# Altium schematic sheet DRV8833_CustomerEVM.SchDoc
size B
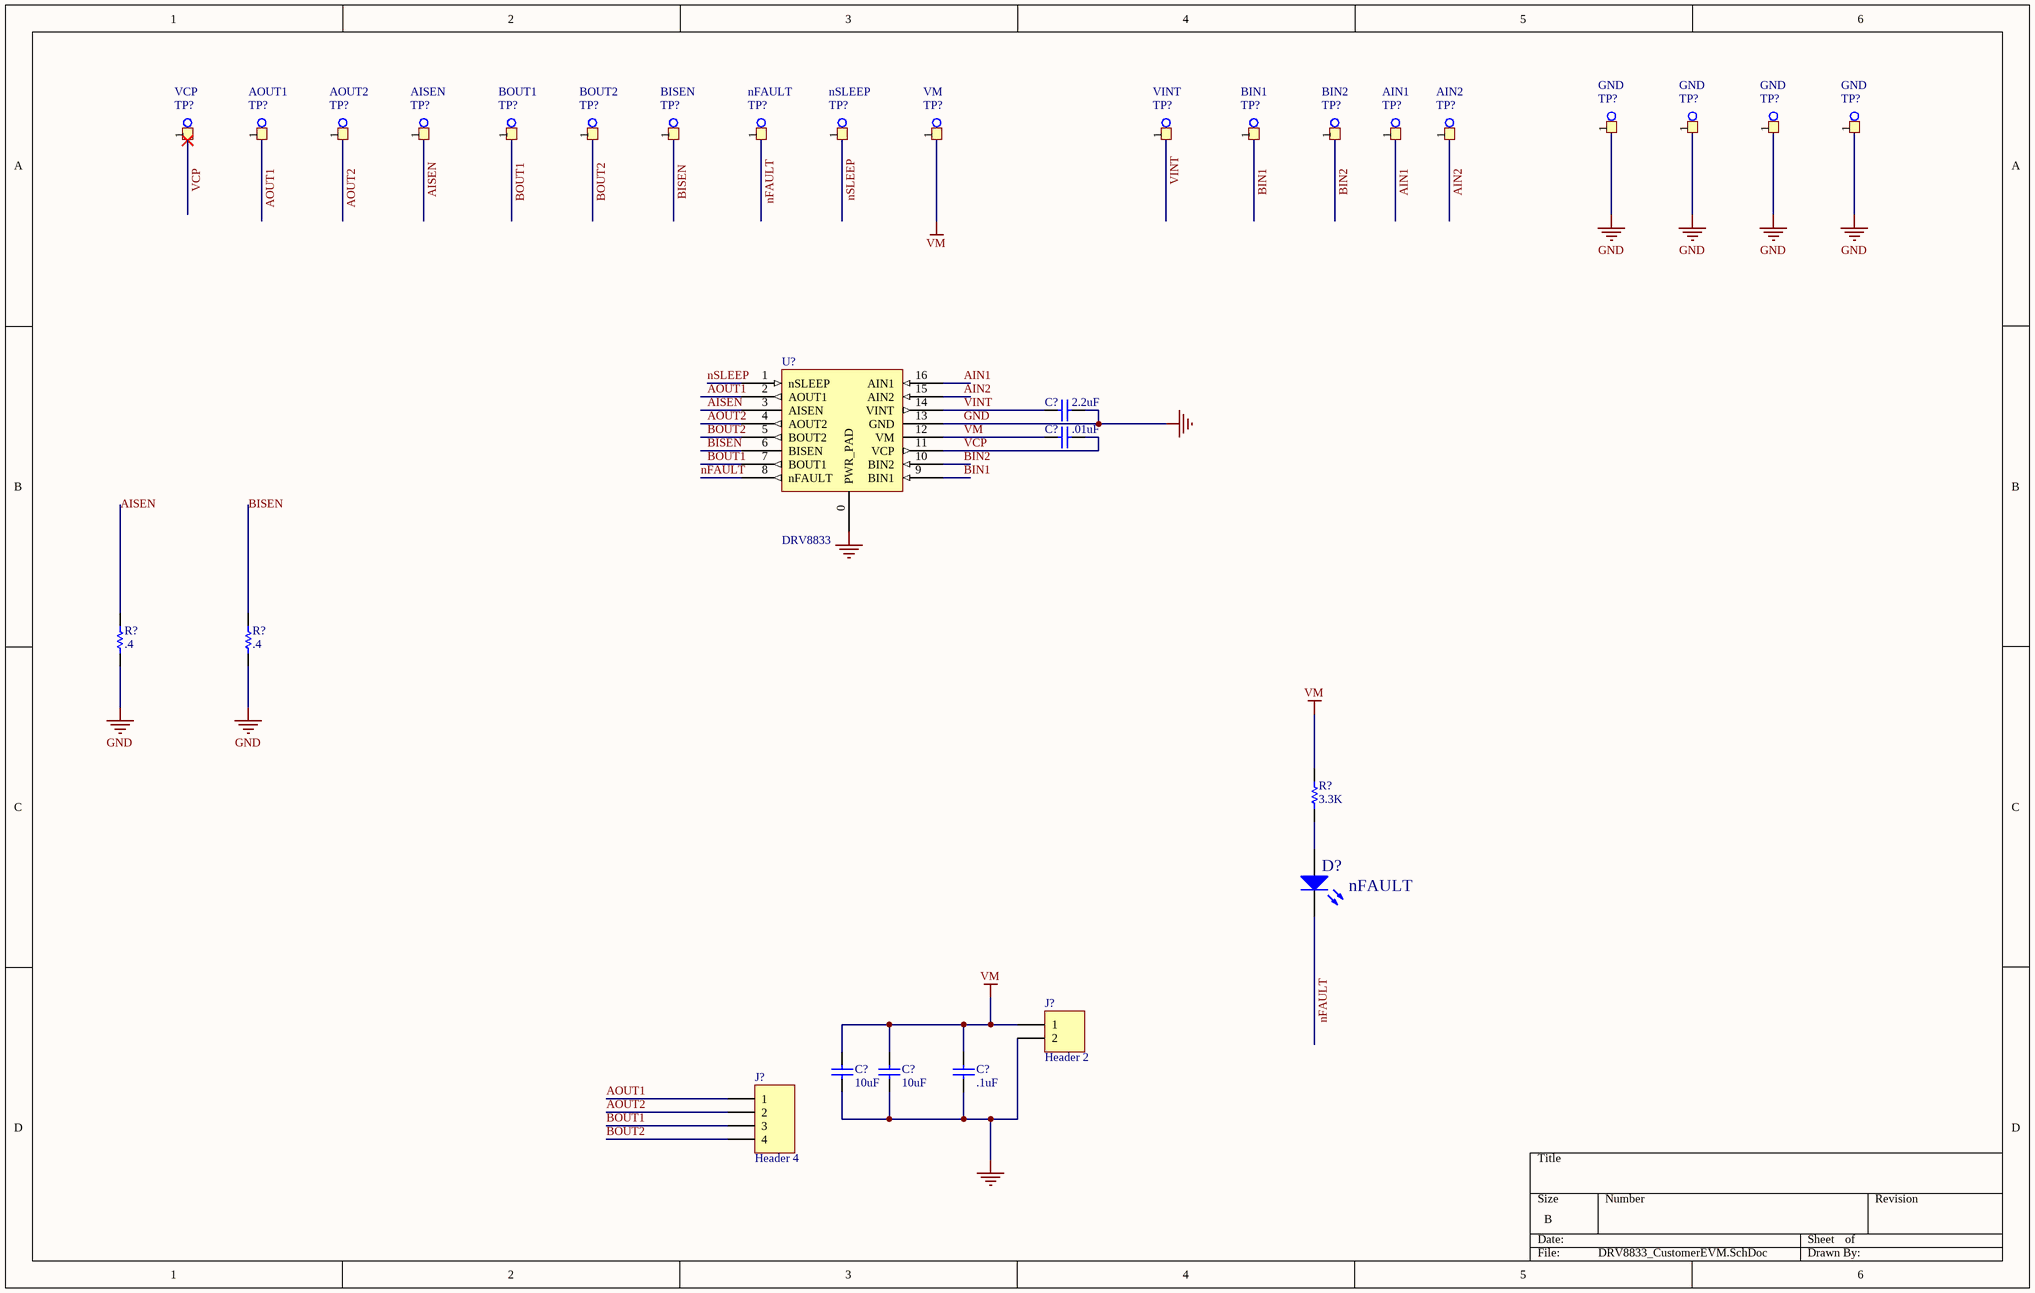
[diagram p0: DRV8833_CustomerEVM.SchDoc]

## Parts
(Parts that share a designator on the sheet are numbered #1, #2 ... from top to bottom, then left to right.)
C?#1  2.2uF  [0805]
C?#2  .01uF  [0805]
C?#3  value 10uF  [0805]
C?#4  value 10uF  [0805]
C?#5  value .1uF  [0805]
D?  nFAULT  [1206]
J?#1  Header 2  [HDR1X2]
J?#2  Header 4  [HDR1X4]
R?#1  value .4  [2512]
R?#2  value .4  [2512]
R?#3  value 3.3K  [0805]
TP?#1  GND  [TEST POINT 0.052]
TP?#2  GND  [TEST POINT 0.052]
TP?#3  GND  [TEST POINT 0.052]
TP?#4  GND  [TEST POINT 0.052]
TP?#5  VCP  [TEST POINT 0.052]
TP?#6  AOUT1  [TEST POINT 0.052]
TP?#7  AOUT2  [TEST POINT 0.052]
TP?#8  AISEN  [TEST POINT 0.052]
TP?#9  BOUT1  [TEST POINT 0.052]
TP?#10  BOUT2  [TEST POINT 0.052]
TP?#11  BISEN  [TEST POINT 0.052]
TP?#12  nFAULT  [TEST POINT 0.052]
TP?#13  nSLEEP  [TEST POINT 0.052]
TP?#14  VM  [TEST POINT 0.052]
TP?#15  VINT  [TEST POINT 0.052]
TP?#16  BIN1  [TEST POINT 0.052]
TP?#17  BIN2  [TEST POINT 0.052]
TP?#18  AIN1  [TEST POINT 0.052]
TP?#19  AIN2  [TEST POINT 0.052]
U?  DRV8833  [OTS-28-16-0.65-01-00 Mimas HTTSOP]

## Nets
GND: C?#1.1 C?#3.1 C?#4.1 C?#5.1 J?#1.2 R?#1.2 R?#2.2 TP?#1.1 TP?#2.1 TP?#3.1 TP?#4.1 U?.0(PWR_PAD) U?.13(GND)
VM: C?#2.2 C?#3.2 C?#4.2 C?#5.2 J?#1.1 R?#3.1 TP?#14.1 U?.12(VM)
AIN1: TP?#18.1 U?.16(AIN1)
AIN2: TP?#19.1 U?.15(AIN2)
AISEN: R?#1.1 TP?#8.1 U?.3(AISEN)
AOUT1: J?#2.1 TP?#6.1 U?.2(AOUT1)
AOUT2: J?#2.2 TP?#7.1 U?.4(AOUT2)
BIN1: TP?#16.1 U?.9(BIN1)
BIN2: TP?#17.1 U?.10(BIN2)
BISEN: R?#2.1 TP?#11.1 U?.6(BISEN)
BOUT1: J?#2.3 TP?#9.1 U?.7(BOUT1)
BOUT2: J?#2.4 TP?#10.1 U?.5(BOUT2)
nFAULT: D?.2(K) TP?#12.1 U?.8(nFAULT)
nSLEEP: TP?#13.1 U?.1(nSLEEP)
VCP: C?#2.1 TP?#5.1 U?.11(VCP)
VINT: C?#1.2 TP?#15.1 U?.14(VINT)
NetD?_1: D?.1(A) R?#3.2

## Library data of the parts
C?#1 = Cap: Capacitor; Manufacturer: Murata Electronics; Part #: 490-1698-1-ND; MFG Part Number: GRM21BR70J225KA01L; # of Posts: 0
C?#2 = Cap: Capacitor; Manufacturer: Kemet; Part #: 399-1158-1-ND; MFG Part Number: C0805C103K5RACTU; # of Posts: 0
C?#3 C?#4 = Cap: Capacitor; Manufacturer: TDK Corporation; Part #: 445-4115-1-ND; MFG Part Number: C2012X5R1C106M
C?#5 = Cap: Capacitor; Manufacturer: Kemet; Part #: 399-1170-1-ND; MFG Part Number: C0805C104K5RACTU
D? = LED3: LED RED CLEAR 1206 SMD; MFG Part Number: HBR1105W-TR; Manufacturer: Stanley Electric & Co; Part #: 404-1033-1-ND; Value: LED RED
J?#1 = Header 2: Header, 2-Pin; Manufacturer: Any; # of Posts: 0
J?#2 = Header 4: Header, 4-Pin; Manufacturer: Any
R?#1 = Res1: Resistor; Manufacturer: Stackpole Electronics Inc; Part #: CSRN2512FKR400CT-ND; MFG Part Number: CSRN2512FKR400
R?#2 = Res1: Resistor; Manufacturer: Stackpole Electronics In; Part #: CSRN2512FKR400CT-ND; MFG Part Number: CSRN2512FKR400
R?#3 = Res1: Resistor; Manufacturer: Yageo; Part #: 311-3.3KARCT-ND; MFG Part Number: RC0805JR-073K3L
TP?#1-TP?#4 = TEST POINT: Glass Beaded Test Point; Manufacturer: Kobiconn; MFG Part Number: 151-103-RC; Part #: 151-103-RC (Black) Mouser; Value: BLACK
TP?#5-TP?#13 TP?#15-TP?#19 = TEST POINT: Glass Beaded Test Point; Manufacturer: Kobiconn; MFG Part Number: 151-101-RC; Part #: 151-101-RC (white) Mouser; Value: WHITE
TP?#14 = TEST POINT: Glass Beaded Test Point; Manufacturer: Kobiconn; MFG Part Number: 151-107-RC; Part #: 151-107-RC (red) Mouser; Value: RED
U? = DRV8833_HTSSOP: H Bridge OTS-28-16-0.65-01-00 Mimas HTTSOP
